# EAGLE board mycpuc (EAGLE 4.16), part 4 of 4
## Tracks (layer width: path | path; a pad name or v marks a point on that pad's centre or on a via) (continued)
N_DSR0  (via drill 0.3 pad 0.81) (continued)
  Top 0.254: IC21.P82 83.36,38.75 84.2,37.91 v84.2,37.76 | v88.9,22.16 88.9,22.91 82.85,28.96 82.85,32.61 v82.6,32.91 | D9.1 108.9,23.51 v109.85,22.56 | v117.45,26.06 117.75,26.01 120.1,23.66 120.1,22.56 120.14,22.52 R57.1
  Bottom 0.254: v117.45,26.06 117.45,24.86 113.5,20.96 109.85,20.96 | 109.85,20.96 v109.85,22.56 | v84.2,37.76 82.6,36.16 v82.6,32.91 | 109.85,20.96 90.1,20.96 v88.9,22.16
N_DSR1  (via drill 0.3 pad 0.81)
  Top 0.254: v84.35,8.61 83.85,9.11 83.85,9.81 85.35,11.31 87.4,11.31 87.7,11.61 87.7,20.06 86.85,20.91 82.8,20.91 81.95,21.76 81.95,22.81 v77.95,26.81 | v82.05,27.26 81.4,27.96 81.4,30.91 80.8,31.51 80.8,34.26 81,34.26 81.01,34.25 IC21.P73
  Bottom 0.203: 75.8,11.06 75.79,11.07 D12.2 75.79,11.3 76.7,12.21 80.8,12.21
  Bottom 0.254: v84.35,8.61 84.35,8.66 80.8,12.21 | R63.1 75.47,9.78 75.8,10.11 75.8,11.06 | v77.95,26.81 81.65,26.81 v82.05,27.26
N_DTR0  (via drill 0.3 pad 0.81)
  Top 0.254: IC21.P80 82.59,37.75 v82.85,38.01 | v86.9,23.01 86.9,23.86 82.1,28.66 82.1,31.56 v81.9,31.81
  Bottom 0.254: IC15.13 118.8,24.45 114.1,19.76 88.75,19.76 86.9,21.61 v86.9,23.01 | v82.85,38.01 81.65,36.81 81.65,32.06 81.85,31.81 v81.9,31.81
N_DTR1  (via drill 0.3 pad 0.81)
  Top 0.254: v98.4,2.66 94.75,6.31 94.75,10.76 91.9,13.63 91.9,27.66 82.8,36.76 IC21.P78
  Bottom 0.254: IC16.13 97.92,3.94 98.4,3.46 v98.4,2.66
N_FAULT
  Top 0.254: IC23.74 121.6,59.16 121.75,59.31 121.75,62.36 122.7,63.31 J15.4
  Bottom 0.254: R144.1 120.42,81.39 121.4,80.41 121.4,77.51 122.7,76.21 J15.4
N_HALT
  Top 0.254: IC21.P118 74.25,59.66 64.65,69.26 51.4,69.26 48.9,71.76 48.9,77.66 47.35,79.21 46.65,79.21 J4.53
  Bottom 0.254: J4.53 45.25,80.51 42.6,80.51 36.95,86.16 24.75,86.16 22.8,84.21 19.65,84.21 | R37.2 18.14,93.22 18.15,93.21 C51.2 19.17,93.24 19.65,92.76 19.65,86.26 19.4,86.01 16.85,86.01 16.45,85.61 16.45,84.61 16.85,84.21 19.65,84.21 | 19.65,82.7 19.8,82.66 | D6.2 19.65,82.7 | 19.65,82.7 19.65,84.21
N_IOCS16
  Top 0.254: J12.32 127.65,55.06 124.75,52.16 IC23.60 | IC23.60 120.5,52.16 | IC23.60
  Route15 0.254: J12.32 129.59,53.86 137.2,53.86 138.4,55.06 138.4,55.11 J13.32
  Bottom 0.254: R123.1 143.2,56.41 139.72,56.41 J13.32
N_IOENA0  (via drill 0.3 pad 0.81)
  Top 0.254: IC21.P17 52.54,43.75 v52.45,43.76 | IC9.21 37.53,36.04 38.4,36.91 v40.35,36.91
  Bottom 0.254: v40.35,36.91 40.65,37.21 40.65,37.71 41.25,38.31 42.25,38.31 43.25,37.31 47.55,37.31 49.4,39.16 49.4,42.41 50.75,43.76 v52.45,43.76 | v52.45,43.76 52.5,43.76 | J4.50 44.57,74.14 45.85,72.86 47.15,72.86 49.7,75.41 52.35,75.41 54.35,73.41 54.35,45.66 v52.45,43.76
N_IOENA1  (via drill 0.3 pad 0.81)
  Top 0.254: IC21.P18 53.34,43.25 53,42.91 51.65,42.91 v51.5,42.76 | IC9.20 38.03,35.39 38.6,35.96 40.85,35.96 41.45,36.56 41.45,37.06 v41.7,37.31
  Bottom 0.254: v41.7,37.31 41.7,36.31 43.25,34.76 47.2,34.76 48,35.56 48,36.11 50.25,38.41 50.25,41.96 51.05,42.76 v51.5,42.76 51.5,42.81 51.75,42.56 52.85,42.56 55,44.71 55,73.66 52.55,76.11 48.5,76.11 46.53,74.14 46.55,74.11 J4.49
N_IOENA2  (via drill 0.3 pad 0.81)
  Top 0.254: v51.35,41.46 51.65,41.46 52.44,42.25 IC21.P20 | IC9.19 38.93,34.74 v39.2,35.01
  Bottom 0.254: v39.2,35.01 39.2,32.61 42.55,29.26 42.55,27.91 43.25,27.21 47.55,27.21 50.15,29.81 50.15,36.66 51.35,37.86 v51.35,41.46 51.4,41.41 51.45,41.46 53.15,41.46 55.65,43.96 55.65,73.91 52.7,76.86 46.75,76.86 J4.51
N_LOCAL  (via drill 0.3 pad 0.81)
  Top 0.254: 75.25,54.06 IC21.P116 75.25,59.61 64.9,69.96 54,69.96 52.4,71.56 v51.65,71.56
  Bottom 0.254: v51.65,71.56 51.4,71.51 48.75,68.86 48.75,63.11 47.1,61.46 46.55,61.46 | R20.2 42.86,63.1 43.35,62.61 44.75,62.61 45.9,61.46 46.55,61.46 | 46.55,61.46 J4.39
N_MEMRD  (via drill 0.3 pad 0.76, 0.3 pad 0.81)
  Top 0.152: 34.05,79.51 34.05,83.01
  Top 0.203: IC11.31 34.67,84.03 34.05,83.01 | 34.05,79.51 34.05,78.16 34.6,77.61 34.6,74.11 34.25,73.76 34.25,72.56 34.48,72.33 34.48,71.03 34.7,70.86 | 34.7,70.86 | 34.7,70.86 IC10.31 | v34.1,68.81 34.7,68.85 | 34.7,66.61 33.75,65.66 33.75,63.06 41.95,54.86
  Top 0.254: v66.45,28.56 66.6,28.56 67.75,29.71 IC21.P50 | 34.7,68.85 34.7,70.86 | 34.7,66.61 34.7,68.81 v34.1,68.81 | 41.95,54.86 41.95,47.56 34.9,40.51 v34.9,38.26
  Route15 0.254: v66.45,28.56 66.45,28.11 65.35,27.01 57.1,27.01 56.55,27.56 52.9,27.56 47.35,22.01 43.25,22.01 38.75,26.46 v38.75,29.61
  Bottom 0.203: 34.25,80.76 27.05,80.76 25.3,79.01 25.3,75.91 24.3,74.91 | v34.1,68.81 34.1,68.96
  Bottom 0.254: IC12.28 26.38,66.13 25,67.51 25,71.16 24.3,71.86 24.3,74.91 | 34.25,80.76 36.7,78.31 36.7,71.56 34.1,68.96 | v34.9,38.26 34.9,28.26 35.5,27.66 38.35,27.66 38.75,28.06 v38.75,29.61
N_MEMWR  (via drill 0.3 pad 0.76, 0.3 pad 0.81)
  Top 0.152: 26.43,84.01 26.43,87.26 | 26.4,68.56 26.4,72.41
  Top 0.203: 26.43,84.01 25.77,83.01 25.77,80.98 | 25.77,80.98 25.78,80.99 IC10.13 | 25.77,80.98 25.77,76.21 26.4,75.21 26.4,72.41 | 26.4,68.56 25.95,68.11 25.95,66.86 27.2,65.61 27.2,62.86 33.15,56.91 v33.15,55.11
  Top 0.254: IC21.P51 68.25,28.91 v67.9,28.56 | IC11.13 25.78,89.65 26.43,89.01 26.43,87.26 | v40,38.91 v40,44.21
  Route15 0.254: v67.9,28.56 65.7,26.36 62.55,26.36 60.35,24.16 51.95,24.16 47.35,19.56 42.95,19.56 37.8,24.71 v37.8,28.61
  Bottom 0.203: v37.8,28.61 37.8,28.56 | IC12.11 31.35,45.19 31.35,46.26 31.25,46.46 31.25,47.46 | v40,44.21 40.2,44.41 41.3,44.41 42.05,45.16 42.05,46.16
  Bottom 0.254: v40,38.91 39.9,38.71 39.9,37.76 37.8,35.66 v37.8,28.61 | 31.25,47.46 33.15,49.36 33.15,52.81 | 33.15,52.81 v33.15,55.11 | 42.05,46.16 42.05,47.46 36.7,52.81 33.15,52.81
N_PRESET
  Top 0.254: IC23.77 118.03,63.29 120.15,65.41 120.15,76.31 120.16,76.3 J15.6
N_RCOD  (via drill 0.3 pad 0.81)
  Top 0.254: IC9.18 39.88,34.09 v40.62,34.83 40.73,34.83 40.8,34.86 43.25,37.31 48.55,37.31 52.99,41.75 IC21.P21
  Bottom 0.254: v40.62,34.83 40.6,34.81 40.6,32.36 43.25,29.71 45.3,29.71 J4.15
N_READ  (via drill 0.3 pad 0.81)
  Top 0.254: IC9.17 41.23,33.44 v42,34.21 42.5,34.71 47.25,34.71 48,35.46 48,35.71 53.05,40.76 58.75,40.76 58.79,40.75 IC21.P23
  Bottom 0.254: J4.16 42,32.96 v42,34.21
N_RESET  (via drill 0.3 pad 0.76, 0.3 pad 0.81)
  Top 0.254: IC21.P53 69.25,27.61 68.55,26.91 56.2,26.91 v55.9,26.61 | v55.95,28.56 55.45,28.56 54.15,27.26 54.15,24.51 48.8,19.16 48.8,15.76 47.55,14.51 42.85,14.51 38.75,18.61 v32,18.61
  Route2 0.254: v30.45,46.66 30.45,39.86 32,38.31 v32,18.61 | v104.05,96.91 103.35,97.61 53.75,97.61 v52.35,96.21
  Bottom 0.203: IC12.12 30.88,46.09 30.87,46.09 30.45,46.51 v30.45,46.66 | v55.95,28.56 56.2,28.56
  Bottom 0.254: IC2.2 127.81,92.67 127.65,92.51 122.4,92.51 121.85,91.91 120.65,91.91 120.37,91.93 R10.1 120.32,91.93 120.3,91.91 119.2,91.91 115.15,95.96 113.9,95.96 113.2,96.66 104.3,96.66 v104.05,96.91 | 55.9,26.56 v55.9,26.61 56.2,26.91 56.2,28.56 56.2,37.21 56.95,37.96 56.95,89.86 56.3,90.51 54.85,90.51 53.4,91.96 53.4,93.41 52.35,94.46 v52.35,96.21 | D22.3 53.43,28.54 53.65,28.76 56,28.76 55.95,28.71 v55.95,28.56
N_RI0  (via drill 0.3 pad 0.81)
  Top 0.254: v78.85,22.01 78.85,22.41 73.6,27.66 73.6,30.01 72.75,30.86 IC21.P60 | D8.1 115.3,23.51 116.25,22.56 117.1,22.56 117.2,22.46 R59.1 118.37,22.49 118.65,22.21 v118.65,22.06
  Bottom 0.254: v118.65,22.06 118.4,22.21 114.75,18.56 82.3,18.56 v78.85,22.01
N_RI1  (via drill 0.3 pad 0.81)
  Top 0.254: v92.15,6.51 92.15,6.61 92.35,6.81 92.35,10.26 89.8,12.83 89.8,27.06 82.11,34.75 IC21.P74
  Bottom 0.254: v92.15,6.51 92.05,6.41 92.05,3.76 90.9,2.61 72.2,2.61 71.9,2.91 71.9,3.96 | 71.9,3.96 71.9,4.01 73,4.01 73.02,3.99 R65.1 | D11.2 71.61,4.25 71.9,3.96
N_RTS0  (via drill 0.3 pad 0.81)
  Top 0.254: v83.25,21.91 83.25,22.81 76.75,29.36 IC21.P68
  Bottom 0.254: IC15.12 118.55,25.1 113.8,20.36 89.3,20.36 87.9,21.76 87.9,23.41 87.35,23.96 86.55,23.96 84.5,21.91 v83.25,21.91
N_RTS1  (via drill 0.3 pad 0.81)
  Top 0.254: v93.55,2.51 94.3,1.76 98.95,1.76 99.35,2.16 99.35,3.01 95.45,6.91 95.45,11.01 92.6,13.86 92.6,27.91 83.2,37.26 IC21.P79
  Bottom 0.254: IC16.12 94.78,4.59 93.95,3.76 93.95,2.91 v93.55,2.51
N_SELCPLD  (via drill 0.3 pad 0.81)
  Top 0.254: IC21.P55 70.25,23.41 v70.65,23.01 | LED2.C 110.59,97.05 109.75,96.21 109.75,95.66 v109.7,95.61 | IC23.96 108.53,62.83 106.55,64.81 100.9,64.81 v100.15,64.06
  Route2 0.254: v109.7,95.61 110.85,94.46 110.85,90.46 109.6,89.21 109.6,84.41 106.2,81.01 106.2,70.16 v100.15,64.06
  Bottom 0.254: v70.65,23.01 70.65,23.46 74,26.81 76.7,26.81 77.7,27.81 78.1,27.81 78.6,27.51 80.9,27.51 86.25,32.91 86.25,38.96 85.25,39.96 84.65,39.96 82.75,41.86 82.75,61.61 81.5,62.86 62.05,62.86 59.95,64.96 59.95,87.26 66.7,94.01 69,94.01 70.75,95.76 109.55,95.76 v109.7,95.61 109.7,95.16 110.57,94.29 R117.1
N_SELOUT
  Top 0.254: IC23.92 110.53,65.58 103.8,72.31 98.95,72.31 96.05,75.21 96.05,77.61 94.8,78.86 J15.25
N_STROBE
  Top 0.254: IC23.70 122.6,57.16 123.55,58.11 123.55,61.36 126.45,64.26 126.45,77.71 125.3,78.86 125.26,78.82 J15.1
N_SWITCHES  (via drill 0.3 pad 0.81)
  Top 0.254: IC21.P87 85.21,41.25 v85.55,40.86
  Bottom 0.254: D17.3 96,90.91 | D17.3 95.96,90.9 95.95,90.91 95.95,91.36 96.05,91.46 101.1,91.46 101.08,91.44 D16.3 | D17.3 95.98,91.43 95.95,91.46 91,91.46 90.88,91.34 D18.3 90.93,90.89 90.95,90.91 90.93,90.93 90.93,91.28 90.75,91.46 86,91.46 85.83,91.29 D19.3 85.8,90.96 85.8,91.41 84.1,91.41 82.45,93.06 66.8,93.06 60.55,86.81 60.55,65.31 62.4,63.46 81.75,63.46 83.35,61.86 83.35,43.06 v85.55,40.86
N_WRITE  (via drill 0.3 pad 0.81)
  Top 0.254: 44.04,33.5 44.05,33.51 | 44.04,33.5 J4.18 | IC9.16 42.38,32.79 43.1,33.51 43.79,33.5 44.04,33.5 | IC21.P24 53.59,40.25 49,35.66 v49,35.06
  Bottom 0.254: J4.18 45.25,32.26 47.35,32.26 49,33.91 v49,35.06
NHALTIN  (via drill 0.3 pad 0.81)
  Top 0.254: v13.85,86.71 13.85,85.56 11.35,83.06 8.4,83.06 7.15,81.81 5.35,81.81 5.34,81.8 J1.A29
  Bottom 0.254: J1.A29 6.11,81.76 6.7,82.36 7.8,82.36 R38.1 | 15.76,87.3 D7.2 | R40.1 15.77,87.29 15.76,87.3 | 15.76,87.3 15.74,87.3 15.5,87.06 14.15,87.06 13.8,86.71 v13.85,86.71
OUT0  (via drill 0.3 pad 0.81)
  Top 0.254: IC19.15 112.85,16.51 v112.25,15.96
  Route15 0.254: J10.3 104.45,6.59 104.45,8.41 110.65,14.61 110.65,15.16 111.45,15.96 v112.25,15.96
OUT1  (via drill 0.3 pad 0.81)
  Top 0.254: IC19.1 111.6,13.01 v111.6,14.76
  Route15 0.254: J10.5 106.95,6.55 106.95,9.61 111.6,14.26 v111.6,14.76
OUT2  (via drill 0.3 pad 0.81)
  Top 0.254: IC19.2 v112.85,14.76
  Route15 0.254: J10.7 109.45,6.51 109.45,10.51 112.85,13.91 v112.85,14.76
OUT3  (via drill 0.3 pad 0.81)
  Top 0.254: IC19.3 114.1,13 v114.1,14.76
  Route15 0.254: J10.9 112,6.52 112,11.51 114.1,13.61 v114.1,14.76
OUT4  (via drill 0.3 pad 0.81)
  Top 0.254: 115.4,12.97 115.4,12.96 | 115.4,12.97 IC19.4 | v115.4,14.71 115.4,12.97
  Route15 0.254: J10.11 114.5,6.48 114.5,12.56 115.4,13.46 v115.4,14.71
OUT5  (via drill 0.3 pad 0.81)
  Top 0.254: IC19.5 116.65,12.96 | IC19.5 | v116.65,14.71 IC19.5
  Route15 0.254: J10.13 117.05,6.49 117.05,13.41 116.7,13.76 116.7,14.66 v116.65,14.71
OUT6  (via drill 0.3 pad 0.81)
  Top 0.254: IC19.6 117.9,13.01 v117.9,14.71
  Route15 0.254: J10.15 119.6,6.5 119.6,8.96 117.9,10.66 v117.9,14.71
OUT7  (via drill 0.3 pad 0.81)
  Top 0.254: IC19.7 v119.2,14.71
  Route15 0.254: J10.17 122.1,6.46 122.1,8.41 119.2,11.31 v119.2,14.71
PD0
  Top 0.254: IC23.72 121.9,58.16 122.35,58.61 122.35,62.01 124,63.66 124,77.56 122.74,78.82 J15.3
PD1
  Top 0.254: IC23.76 118.53,62.89 121.4,65.76 121.4,77.66 120.2,78.86 J15.5
PD2
  Top 0.254: IC23.78 117.53,63.69 119.15,65.31 119.15,73.86 118.9,74.11 118.9,77.56 117.64,78.82 J15.7
PD3
  Top 0.254: IC23.81 116.03,74.04 116.35,74.36 116.35,77.56 J15.9
PD4
  Top 0.254: IC23.82 115.53,63.33 115.4,63.46 115.4,73.66 113.8,75.26 113.8,77.61 112.59,78.82 J15.11
PD5
  Top 0.254: IC23.85 114.03,68.58 111.3,71.31 111.3,77.56 J15.13
PD6
  Top 0.254: IC23.86 113.53,67.98 108.75,72.76 108.75,77.56 107.46,78.85 | 107.46,78.85 107.45,78.86 | 107.46,78.85 J15.15
PD7
  Top 0.254: IC23.87 113.03,67.43 106.2,74.26 106.2,77.51 104.9,78.81 J15.17
PEMPTY
  Top 0.254: IC23.91 111.03,66.13 103.75,73.41 100.7,73.41 98.6,75.51 98.6,77.51 J15.23
  Bottom 0.254: R143.1 92.47,74.99 92.85,74.96 95.5,74.96 96,75.46 96,77.46 97.35,78.81 97.34,78.82 J15.23
PS2_CLK  (via drill 0.3 pad 0.81)
  Top 0.254: 141.3,93.11 141.3,93.46 | 141.3,93.11 139.55,91.36 132.25,91.36 131,90.11 v131,86.66 | 141.3,93.11 J9.2
  Bottom 0.254: J9.2 141.3,92.96 148.82,85.41 148.85,84.61 | 148.85,84.55 148.9,84.51 | 148.85,84.55 J8.5 148.85,84.61 | 148.85,84.61 148.85,84.55 | 148.85,84.61 148.85,82.93 150.65,81.13 152.1,81.13 152.6,80.63 152.6,77.26 151.7,76.36 146.8,76.36 146.37,76.79 146.37,77.53 146.42,77.58 R68.1 | 131.02,88.01 131.05,88.01 | 131.02,88.01 R70.2 | T4.3 v130.99,86.66 | v130.99,86.66 130.99,88.01 131.02,88.01 | v130.99,86.66 v131,86.66
PS2_CLK_I  (via drill 0.3 pad 0.81)
  Top 0.254: IC21.P86 84.31,40.75 86.85,38.96 86.85,37.91 88.85,35.91 101.95,35.91 103.9,33.96 v103.9,33.76
  Bottom 0.254: v103.9,33.76 104.9,33.76 109.95,38.81 120,38.81 124.35,43.16 124.35,47.91 127.7,51.26 131.65,51.26 132.5,52.11 132.5,53.31 134.45,55.26 134.45,67.76 132.5,69.71 132.5,78.61 135,81.11 T2.3 135.01,85.12 T2.3 134.99,88.11 | 134.99,88.11 R72.1 | 134.99,88.11 135,88.11
PS2_CLK_O  (via drill 0.3 pad 0.81)
  Top 0.254: IC21.P85 84.06,40.25 86.25,38.71 86.25,37.61 88.55,35.31 101.35,35.31 102.7,33.96 v102.7,33.76
  Bottom 0.254: 102.7,33.66 v102.7,33.76 102.7,34.16 103.15,34.61 104.75,34.61 109.5,39.41 119.65,39.41 123.7,43.46 123.7,49.96 127.6,53.86 131.85,53.86 133.7,55.71 133.7,67.36 131.7,69.36 131.7,82.66 T4.1
PS2_DAT_I  (via drill 0.3 pad 0.81)
  Top 0.254: IC21.P84 83.81,39.75 85.65,38.41 85.65,37.31 88.25,34.71 100.75,34.71 101.5,33.96 v101.5,33.71
  Bottom 0.254: v101.5,33.71 101.5,34.11 102.65,35.26 104.35,35.26 109.1,40.01 119.25,40.01 123.05,43.81 123.05,51.91 127.45,56.31 131.7,56.31 132.95,57.56 132.95,66.81 130.9,68.86 130.9,76.71 127,80.66 127,85.06 126.95,85.11 126.96,85.12 T3.3 127,88.11 127.04,88.11 R73.1
PS2_DAT_O  (via drill 0.3 pad 0.81)
  Top 0.254: IC21.P83 83.61,39.25 85.05,38.16 85.05,37.01 87.95,34.11 99.9,34.11 v100.3,33.71
  Bottom 0.254: v100.3,33.71 100.3,33.96 102.25,35.91 104,35.91 108.7,40.61 118.9,40.61 122.35,44.06 122.35,53.51 127.75,58.91 131.65,58.91 132.2,59.46 132.2,66.46 130.1,68.51 130.1,76.31 124.05,82.41 124.05,82.76 123.93,82.88 T5.1
PS2_DATA  (via drill 0.3 pad 0.81)
  Top 0.254: v123,86.66 123,89.41 125.75,92.16 136.1,92.16 137,93.06 137,94.91 137.9,95.81 142.6,95.81 143.8,94.66 J9.3
  Bottom 0.254: J9.3 143.8,93.06 146.2,90.66 147.6,90.66 152.6,85.66 152.6,83.71 | J8.1 151.3,82.41 | J8.1 | 152.6,83.71 J8.1 | R69.1 144.07,76.74 145.1,75.71 152.15,75.71 153.9,77.46 155.65,77.46 157.8,79.61 157.8,82.56 156.65,83.71 152.6,83.71 | R71.2 123.01,88.01 122.98,88.01 122.98,86.61 | T5.3 122.98,86.61 | 122.98,86.61 v123,86.66
Q1_3V3
  Top 0.254: 68.66,14.8 68.65,14.81 68.65,17.56 68.67,17.54 L4.1 | Q1.1 65.3,14.86 68.6,14.86 68.66,14.8 | 68.66,14.8 C88.1
  Top 0.406: Q1.4 61.7,13.66 62,13.36 68.4,13.36 68.65,13.61 68.65,14.81
Q2_3V3
  Top 0.254: C89.1 50.21,15.55 50.25,15.51 50.23,15.49 L5.1 | 53.65,15.61 53.8,15.46 53.79,15.45 Q2.4 53.68,15.38 53.7,15.36 53.7,13.66 54,13.36 56.38,13.36 56.7,13.69 56.7,14.96 57.19,15.45 Q2.1
  Top 0.406: C89.1 53.65,15.61
RXD0  (via drill 0.3 pad 0.81)
  Top 0.254: v75.65,22.21 75.65,22.61 71.5,26.76 71.5,28.11 71.25,28.36 IC21.P57 | v107.6,25.41 D9.2
  Bottom 0.254: R56.1 108.23,26.24 107.6,25.61 v107.6,25.41 104.55,22.36 91.1,22.36 88.05,25.41 86.05,25.41 84.15,23.51 77,23.51 v75.65,22.21
RXD1  (via drill 0.3 pad 0.81)
  Top 0.254: v86.2,7.31 86.9,7.31 87.45,6.76 89.3,6.76 89.75,7.21 89.75,10.91 88.4,12.26 88.4,20.36 87.25,21.51 85.45,21.51 77.25,29.71 IC21.P69
  Bottom 0.203: 77.7,11.06 D12.1 | 78,8.96 R62.1
  Bottom 0.254: v86.2,7.31 86.15,7.31 85.85,7.61 83.4,7.61 82.8,8.21 82.8,9.16 80.9,11.06 77.7,11.06 77.7,10.06 78,9.76 78,8.96
SCL  (via drill 0.3 pad 0.81)
  Top 0.254: IC23.93 110.03,64.23 v109.65,64.61
  Bottom 0.254: IC24.6 111.22,63.04 v109.65,64.61
SDA  (via drill 0.3 pad 0.81)
  Top 0.254: IC23.94 109.53,63.48 108.75,64.26 v108.75,65.51
  Bottom 0.254: IC24.5 113.3,61.76 113.25,61.81 110.8,61.81 108.6,64.01 108.6,65.36 v108.75,65.51 108.9,65.51 110.28,66.89 R151.1
SELIN
  Top 0.254: IC23.79 117.03,73.69 117.6,74.26 117.6,76.26 J15.8
  Bottom 0.254: R145.1 116.35,81.19 116.35,77.56 117.65,76.26 117.64,76.26 J15.8
TCK  (via drill 0.3 pad 0.81)
  Top 0.254: v79.15,61.11 79,61.11 v79,58.71
  Bottom 0.254: R2.2 74.71,59.2 74.71,59.97 75.1,60.36 77.45,60.36 79.05,58.81 | 79.05,58.81 79.05,58.26 81.5,55.81 81.5,41.26 84,38.76 84.55,38.76 85.05,38.26 85.05,33.61 80.3,28.86 79.05,28.86 78.55,29.16 77.15,29.16 76.1,28.11 73.4,28.11 69.05,23.71 69.05,21.96 69.65,21.36 69.65,18.81 68.55,17.71 62.8,17.71 61.34,19.17 IC1.6 | 79.05,58.81 v79,58.71 | J2.5 56.75,93.01 61.25,93.01 61.95,92.31 61.95,91.31 58.75,88.11 58.75,61.41 62.1,58.06 71.9,58.06 72.65,58.81 72.65,60.51 73.8,61.66 78.6,61.66 v79.15,61.11
TDI  (via drill 0.3 pad 0.81)
  Top 0.254: v60.3,26.01 60.1,26.16 56.75,26.16 55.85,25.26 v55.9,25.21
  Bottom 0.254: IC1.4 60.04,25.8 v60.3,26.01 | v55.9,25.21 55.85,25.26 56.8,26.21 56.8,36.91 57.55,37.66 57.55,89.86 58.05,90.36 58.05,91.46 58.03,91.68 J2.4
TDO  (via drill 0.3 pad 0.81)
  Top 0.254: IC21.P109 78.75,55.01 78.95,55.21 79.55,55.21 81.85,57.51 | v81.85,57.66 81.85,57.51 | 81.85,57.51 82.6,57.51 85.95,54.16 85.95,52.66 87.8,50.81 92.2,50.81 92.8,51.41 93.7,51.41 R154.1
  Bottom 0.254: v81.85,57.66 80.95,58.56 80.95,60.86 79.55,62.26 71.9,62.26 70.84,61.2 D24.3
TDO_JTAG
  Bottom 0.254: D23.1 62.47,59.39 59.35,62.51 59.35,87.71 66.25,94.61 66.25,96.46 | 55.49,91.7 55.45,91.66 | 55.49,91.7 J2.6 | 55.49,91.7 55.55,91.76 55.55,92.26 54.15,93.66 54.15,96.76 55.85,98.46 65.5,98.46 66.25,97.71 66.25,96.46 | 66.25,96.46 R116.1
TMS
  Bottom 0.254: R1.2 73.81,56.9 73.35,57.36 | 73.35,57.36 73.35,60.16 74.2,61.01 77.9,61.01 79.1,59.81 79.5,59.81 80.1,59.21 80.1,58.11 82.15,56.06 82.15,41.51 84.3,39.36 84.9,39.36 85.65,38.61 85.65,33.26 80.55,28.16 78.85,28.16 78.35,28.46 77.4,28.46 76.4,27.46 73.65,27.46 69.7,23.51 69.7,22.21 70.35,21.56 70.35,18.41 68.95,17.01 62.55,17.01 60.69,18.87 IC1.5 | 73.35,57.36 61.8,57.36 58.15,61.01 58.15,89.36 J2.2
TXD0  (via drill 0.3 pad 0.81)
  Top 0.254: IC21.P63 74.25,28.71 80.55,22.41 v80.55,22.01
  Bottom 0.254: IC15.14 119.05,23.8 114.4,19.16 83.35,19.16 v80.55,22.01
TXD1  (via drill 0.3 pad 0.81)
  Top 0.254: v94.95,3.26 94.95,4.66 94.05,5.56 94.05,10.56 91.2,13.41 91.2,27.46 82.4,36.26 81.15,36.26 81.14,36.25 IC21.P77
  Bottom 0.254: IC16.14 94.86,3.29 v94.95,3.26
VALSN
  Top 0.254: IC23.25 103.4,47.66 102.78,47.03 102.78,43.28 102.78,43.29 TP1.P$1
VBAT  (via drill 0.3 pad 0.81)
  Route15 0.254: 31.78,10.48 31.8,10.46 | 31.78,10.48 BAT1.POS1 31.78,4.58 34.65,1.71 143.9,1.71 152.55,10.36 152.55,45.16 155.35,47.96 155.35,60.56 152.1,63.81 144.4,63.81 144.2,64.01 121.75,64.01 v121.05,63.36 | BAT1.POS2 31.76,10.5 31.78,10.48
  Bottom 0.406: v121.05,63.36 121,63.36 120.69,63.04 IC24.3

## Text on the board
Top: Layer 1
Route2: Layer 2
Route15: Layer 3
Bottom: Layer 4 | MyCPU Compact V1.0 by D.Kuschel 2010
